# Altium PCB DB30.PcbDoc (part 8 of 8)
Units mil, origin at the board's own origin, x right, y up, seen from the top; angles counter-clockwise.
Board outline 3236.22 x 4456.69 mil, 8 copper layers (Top Layer, MidLayer1, MidLayer2, GND-Layer5, MidLayer3, VCC, MidLayer4, Bottom Layer), stack 61.8 mil thick; 219 components, 472 nets, 1811 pads, 1561 vias.
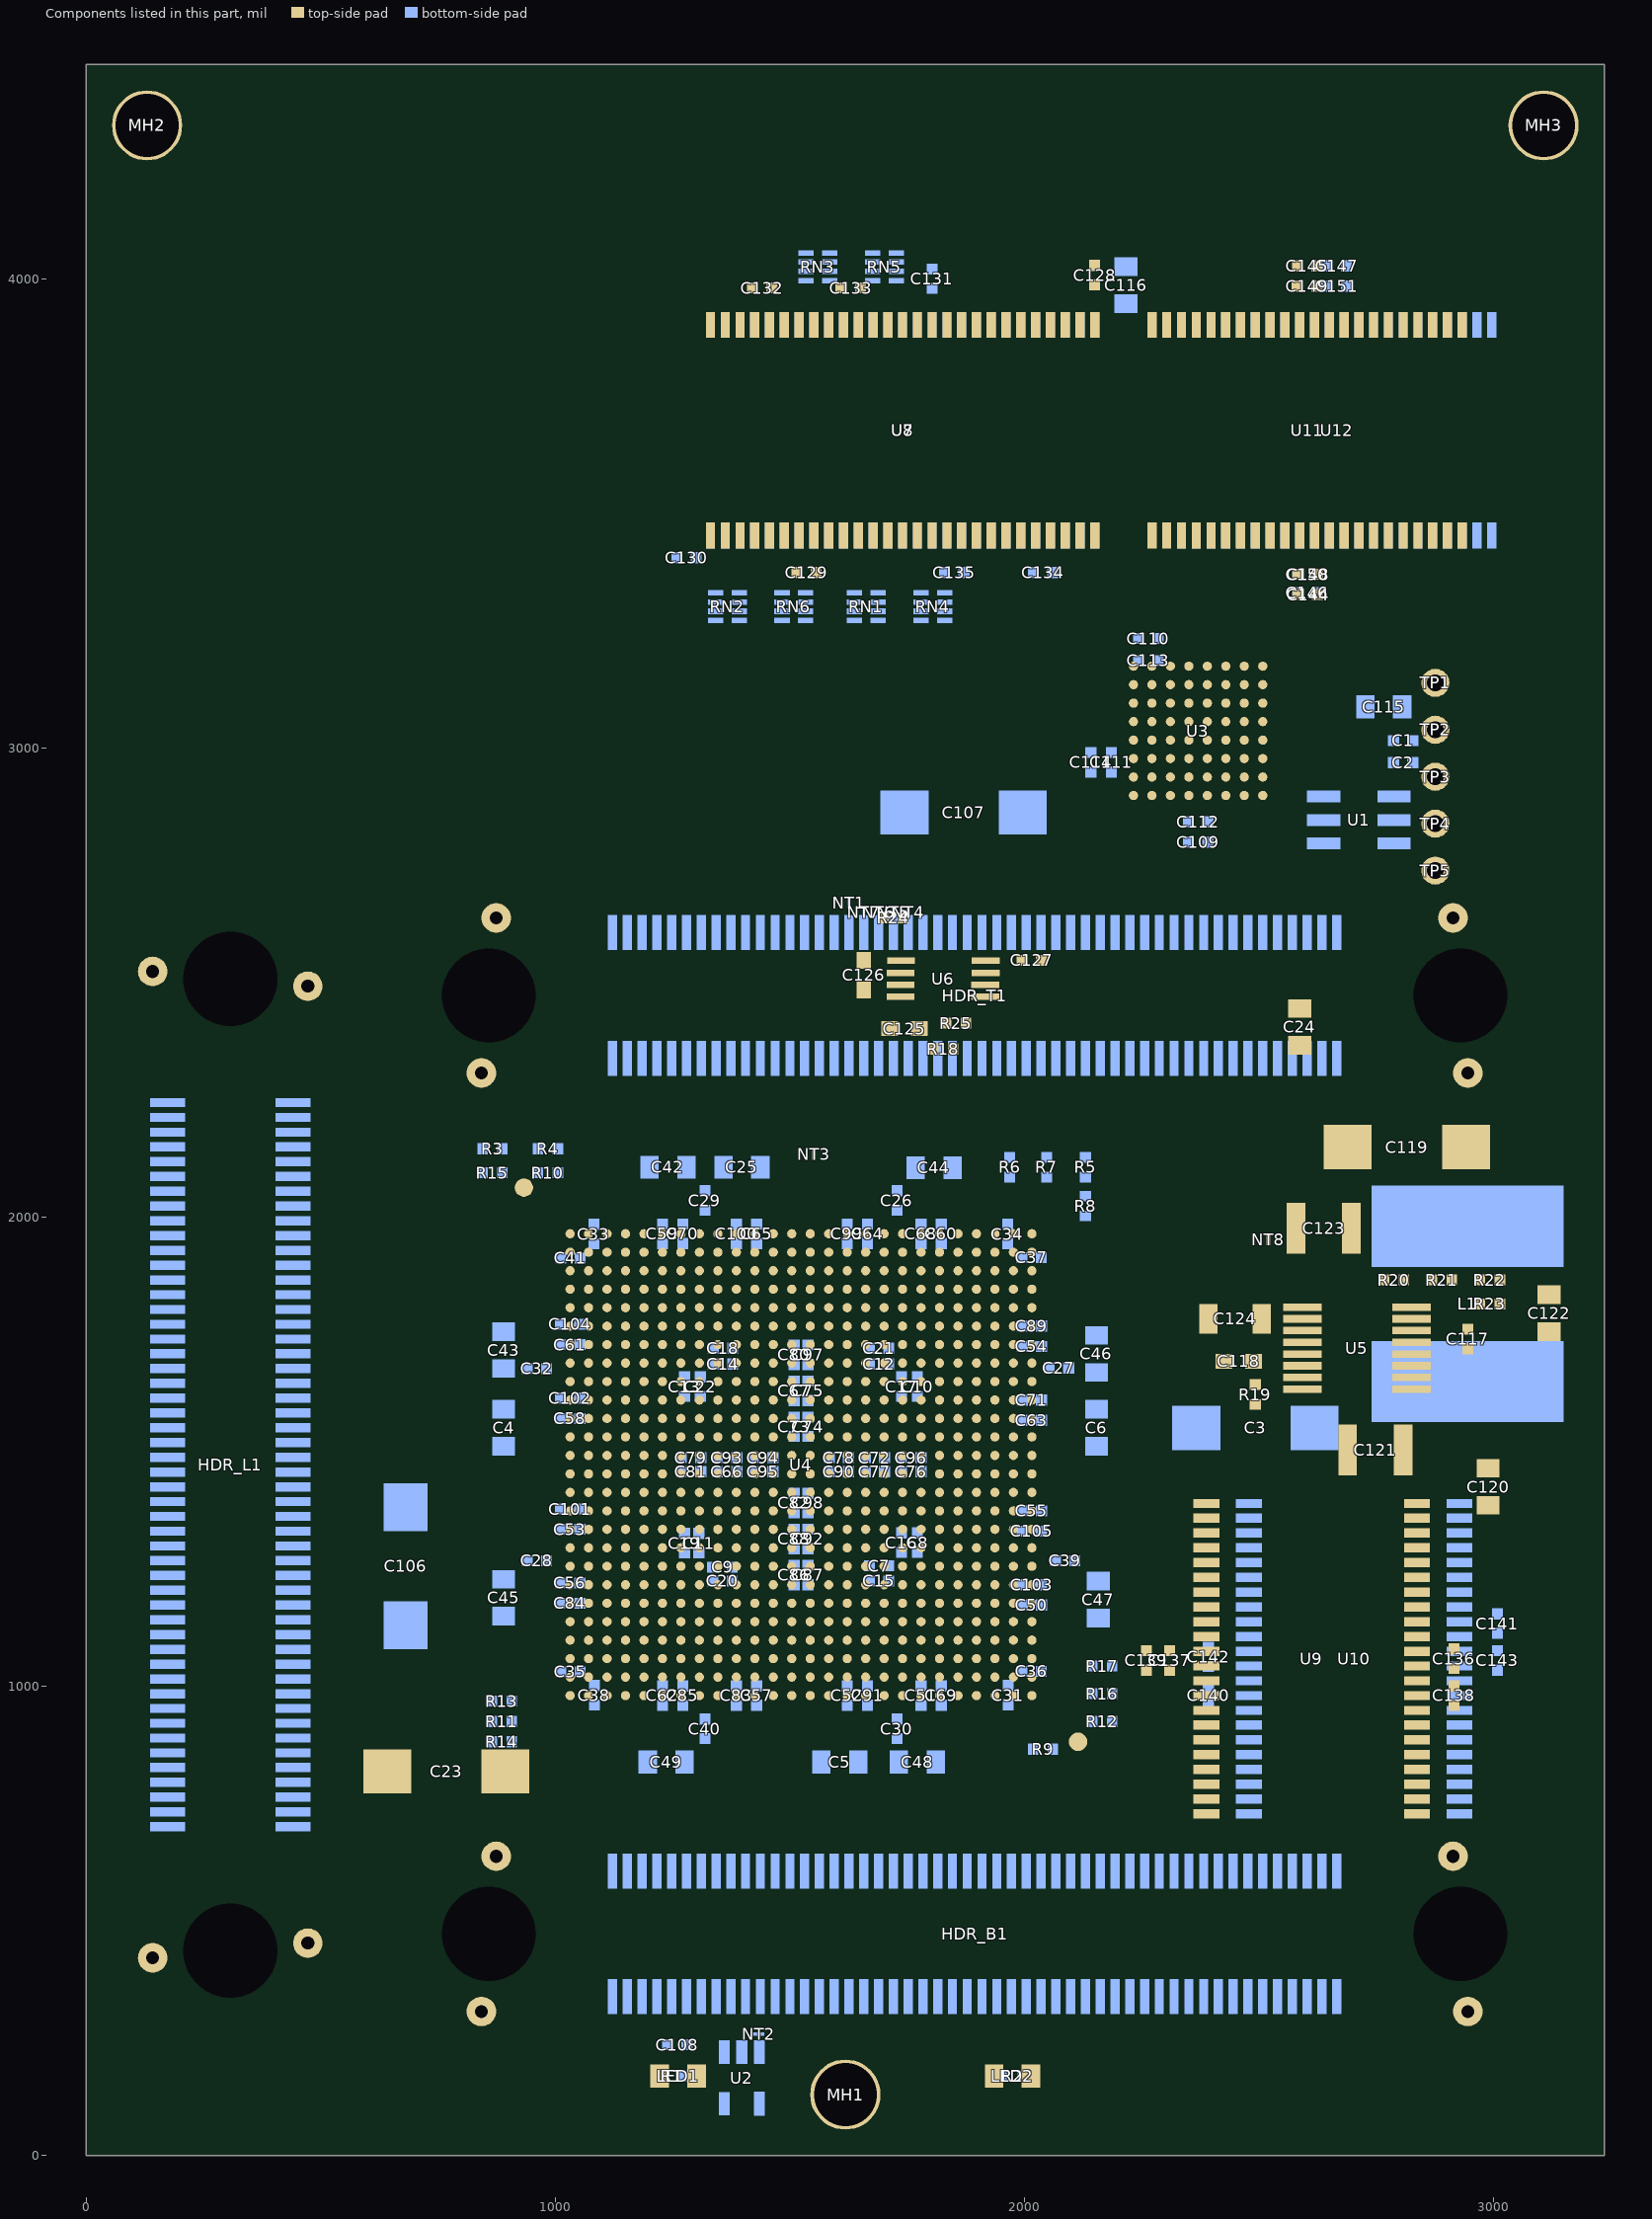
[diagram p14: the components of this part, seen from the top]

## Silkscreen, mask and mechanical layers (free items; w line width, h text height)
Top Overlay:
  rectangle: 998.77,581.74 1627.79,617.74
  rectangle: 998.77,318.48 1627.79,354.48
  rectangle: 2715.79,318.48 2788.79,617.48
  region: 1073.79,617.74 998.77,617.74 998.77,318.48 1073.79,318.48
  rectangle: 2980.31,4181.1 3232.28,4200.79
  rectangle: 2917.32,4181.1 2980.31,4456.69
  region: 1798.1,4447.83 1693.9,4447.83 1693.9,4181.1 1798.1,4181.1
  region: 2968.5,4438.98 2968.5,4456.69 1693.9,4456.69 1693.9,4438.98
  region: 2984.25,4181.1 2984.25,4213.58 1693.9,4213.58 1693.9,4181.1
  region: 1689.96,4181.1 1689.96,4456.69 1670.28,4456.69 1670.28,4181.1
  region: 1598.43,4181.1 1598.43,4456.69 1593.51,4456.69 1593.51,4181.1
  region: 1618.11,4181.1 1618.11,4456.69 1610.24,4456.69 1610.24,4181.1
  region: 1640.75,4181.1 1640.75,4456.69 1628.94,4456.69 1628.94,4181.1
  region: 1664.37,4181.1 1664.37,4456.69 1649.61,4456.69 1649.61,4181.1
  region: 1579.72,4181.1 1579.72,4456.69 1576.77,4456.69 1576.77,4181.1
  rectangle: 2877.95,4204.72 2980.31,4318.9
  region: 1699.8,4334.65 1699.8,4199.8 1846.46,4199.8 1846.46,4334.65
  rectangle: 1301.18,3503.94 2179.13,3596.46
  rectangle: 2238.19,3502.95 2966.89,3595.47
  region: 2787.4,695.23 2787.4,1424.21 2694.88,1424.21 2694.88,695.23
  rectangle: 1775.59,2456.69 1803,2559.05
  rectangle: 1337.26,129.92 1351.38,208.66
  rectangle: 2049.67,129.92 2063.98,208.66
  rectangle: 2736.22,1620.75 2768.58,1820.75
  region: 1840.85,253.71 1833.78,260.78 1756,183 1763.07,175.93
  rectangle: 1756,183 1766,218
  region: 1772.38,166.61 1779.46,159.54 1857.24,237.33 1850.17,244.4
  region: 1814.46,159.54 1814.46,169.54 1779.46,169.54 1779.46,159.54
  region: 3099.71,4136.09 3089.71,4136.09 3089.71,4026.09 3099.71,4026.09
  region: 3064.97,4111.34 3072.04,4104.27 3096.79,4129.02 3089.71,4136.09
  rectangle: 3112.89,4026.09 3122.89,4136.09
  region: 3122.89,4136.09 3115.82,4129.02 3140.56,4104.27 3147.64,4111.34
  region: 123.34,4136.09 113.34,4136.09 113.34,4026.09 123.34,4026.09
  region: 88.59,4111.34 95.66,4104.27 120.41,4129.02 113.34,4136.09
  rectangle: 136.51,4026.09 146.51,4136.09
  region: 146.51,4136.09 139.44,4129.02 164.19,4104.27 171.26,4111.34
  lines w3: 1118.09,192.91 1133.09,202.91 1123.09,202.91 1143.09,217.91 ; 1133.09,207.91 1143.09,217.91 ; 1133.09,212.91 1143.09,217.91 ; 2137.52,187.01 2152.52,197.01 2142.52,197.01 2162.52,212.01 ; 2152.52,202.01 2162.52,212.01 ; 2152.52,207.01 2162.52,212.01
  lines w5: 1078.13,171.78 1103.06,171.78 ; 1103.06,173.36 1126.68,173.36 ; 1104.64,163.12 1126.68,172.05 ; 1104.64,180.97 1126.68,172.05 ; 1105.03,168.63 1126.68,172.96 ; 1105.03,175.46 1126.68,171.13 ; 1126.68,156.3 1126.68,187.79 ; 1126.68,171.78 1150.04,171.78 ; 2097.56,165.88 2122.48,165.88 ; 2122.48,167.45 2146.1,167.45 ; 2124.06,157.21 2146.1,166.14 ; 2124.06,175.07 2146.1,166.14 ; 2124.45,162.73 2146.1,167.06 ; 2124.45,169.56 2146.1,165.23 ; 2146.1,150.39 2146.1,181.89 ; 2146.1,165.88 2169.46,165.88 ; 2260.08,1094.39 2280.3,1122.24 ; 2288.68,987.98 2308.9,1015.83 ; 1126.68,172.05 1103.06,187.79 1103.06,156.3 1126.68,172.05 ; 2146.1,166.14 2122.48,150.39 2122.48,181.89 2146.1,166.14
  lines w7.87: 3232.28,4185.04 3232.28,4200.79 ; 2980.31,4452.76 3232.28,4452.76 ; 2980.31,4452.76 2980.31,4200.79 3232.28,4200.79 ; 2980.31,4452.76 3232.28,4452.76 ; 3232.28,4200.79 3232.28,4452.76
  text "Xilinx®  Spartan™ -3" at 1804.41,4348.85 h125.98
  text "XC3S1500-4FG676C" at 1857.56,4216.97 h118.11
  text "SRAM-256Kx16" at 2352.3,3699.3 h50
  text "DRAM-16Mx16" at 1482.53,3682.61 h50
  text "FLASH" at 2491.1,2767.2 h34
  text "MAX" at 1831.9,2475.9 h22 r90
  text "8860" at 1865.1,2465.2 h25 r90
  text "1831" at 2721.4,1671.7 h40 r90
  text "SRAM-256Kx16" at 2579.8,808.8 h50 r90
  text "DB30.07" at 1027.8,488.46 h98.43
  text "XC3S1500-4FG676C" at 1027.8,430.47 h60
  text "Xilinx Daughter Board" at 1028.31,354.49 h60
  text "DB30.07" at 1625.79,318.46 h60
  text "PROGRAM" at 1145,60 h55.12
  text "POWER" at 1895,60 h55.12
Bottom Overlay:
  drawing of 1169 lines, arcs and shapes, not listed
  text "Xilinx®  Spartan™ -3" at 2913.39,4347.28 h125.98
  text "XC3S1500-4FG676C" at 2860.24,4215.39 h118.11
  text "MANUFACTURE" at 1006.78,3830.86 h40
  text "DATE" at 1007.88,3764.06 h40
  text "SRAM-256Kx16" at 2941.9,3706.2 h50
  text "DRAM-16Mx16" at 1997.78,3682.61 h50
  text "COMPLIANCE:" at 1182.36,3081.45 h45
  text "CLASS 2" at 432.36,2991.45 h40
  text "IPC-A-600H" at 1092.36,2991.45 h40
  text "CLASS 2" at 432.36,2911.45 h40
  text "TYPE 3" at 682.36,2911.45 h40
  text "IPC-6012D" at 1092.36,2911.45 h40
  text "DS2406" at 2711.2,2774.8 h28 r270
  text "1" at 116.93,2272.44 h39.37
  text "1" at 1085.43,2256.69 h39.37
  text "SRAM-256Kx16" at 2728.6,783.2 h50 r270
  text "1" at 1073.62,264.57 h39.37
  text "DB30" at 412.16,123.67 h120
Bottom Solder:
  region: 2455.79,1920.32 2455.79,2040.32 2305.79,2040.32 2305.79,1920.32
PCB Boundary:
  lines w3.94: 1523.62,4456.69 3236.22,4456.69 ; 1523.62,4456.69 3236.22,4456.69 ; 1523.62,4456.69 0,4456.69 0,0 1618.11,0 3236.22,0 3236.22,4456.69 ; 1523.62,4456.69 3236.22,4456.69 ; 1523.62,4456.69 3236.22,4456.69
Mechanical 7:
  lines w7.87: 2448.19,1719.13 2271.61,1846.46 2271.61,2043.31 2448.19,2170.63 ; 2511.22,1754.56 2334.65,1881.89 2334.65,2078.74 2511.22,2206.07 ; 2602.32,1944.88 2681.06,1944.88 ; 2641.69,1905.51 2641.69,1984.25 ; 2661.42,1980.32 2740.16,1980.32 ; 2700.79,1940.94 2700.79,2019.69 ; 2831.26,1719.13 3007.83,1846.46 3007.83,2043.31 2831.26,2170.63 ; 2894.29,1754.56 3070.87,1881.89 3070.87,2078.74 2894.29,2206.07
Keep Away From Edge:
  lines w7.87: 200,200 200,4250 3030,4250 3030,200 200,200

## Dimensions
2865.92,4456.69 to 3106.3,4326.77 on Dimensions
2929.14,472.44 to 3244.09,0 on Dimensions
1618.11,129.92 to 3244.09,0 on Dimensions
307.09,437.01 to -19.69,0 on Dimensions
1618.11,153.54 to 3236.22,19.69 on Dimensions
2929.14,472.44 to 3236.22,-3.94 on Dimensions
0,4456.69 to -19.69,0 on Dimensions
3236.22,0 to 0,4059.06 on Dimensions
307.09,-15.75 to 0,4275.59 on Dimensions
129.92,4342.52 to 0,15.75 on Dimensions
3106.3,4326.77 to 3236.22,0 on Dimensions
2929.13,472.44 to 2929.13,2472.44 on Dimensions
307.09,437.01 to 858.27,472.44 on Dimensions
